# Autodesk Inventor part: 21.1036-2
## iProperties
Created: 2006-12
Part Number: 21.1036-2
Document SubType Name: Modeling
Designer: Andy Moles
Density: 1 g/cm^3
Author: Andy Moles
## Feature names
1. Extrusion1
